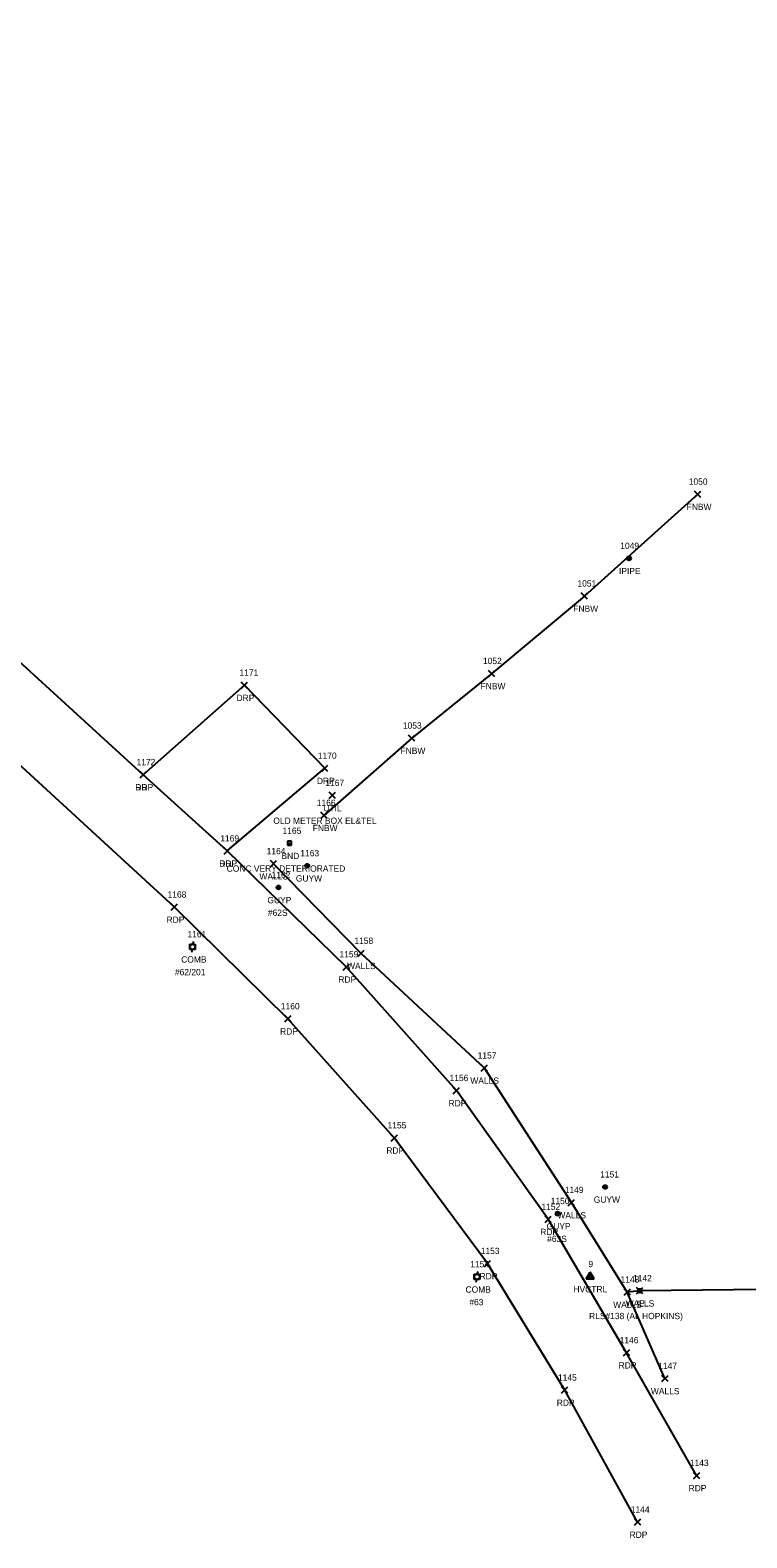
# Model space of a CAD drawing. Extents: x 1519347 to 1522636, y 378779 to 379832.
# Drawn here: x 1521374.1 to 1521601.3, y 378826 to 379303.7 of the extents above; entities that cross this region are included whole.
import ezdxf

# ---------------------------------------------------------------- set-up
doc = ezdxf.new("R2010")
doc.units = 0
for name, color, linetype in [('C_A', 7, 'Continuous'), ('C_I', 7, 'Continuous'), ('CPSM', 7, 'Continuous'), ('L_A', 7, 'Continuous'), ('L_I', 7, 'Continuous'), ('L_TIC', 7, 'Continuous'), ('LFNC', 7, 'Continuous'), ('LWS', 7, 'Continuous'), ('M_A', 7, 'Continuous'), ('M_C', 7, 'Continuous'), ('M_I', 7, 'Continuous'), ('MHBP', 7, 'Continuous'), ('MPIP', 7, 'Continuous'), ('MPIR', 7, 'Continuous'), ('P_A', 7, 'Continuous'), ('P_I', 7, 'Continuous'), ('P_TIC', 7, 'Continuous'), ('PET', 7, 'Continuous'), ('R_A', 7, 'Continuous'), ('R_I', 7, 'Continuous'), ('R_TIC', 7, 'Continuous'), ('RDP', 7, 'Continuous'), ('U_A', 7, 'Continuous'), ('U_C', 7, 'Continuous'), ('U_I', 7, 'Continuous'), ('UDEFAULT', 7, 'Continuous'), ('UP', 7, 'Continuous'), ('UPGW', 7, 'Continuous')]:
    doc.layers.add(name, color=color, linetype=linetype)

msp = doc.modelspace()

# ---------------------------------------------------------------- linework, layer by layer
at = {"layer": 'CPSM'}
for p, q in [((1521550.39, 378908.08), (1521551.64, 378910.25)), ((1521550.39, 378908.08), (1521551.65, 378908.8)), ((1521550.39, 378908.08), (1521552.89, 378908.08)), ((1521552.89, 378908.08), (1521551.64, 378910.25)), ((1521551.65, 378908.8), (1521551.64, 378910.25)), ((1521551.65, 378908.8), (1521551.65, 378908.8)), ((1521551.65, 378908.8), (1521552.89, 378908.08))]:
    msp.add_line(p, q, dxfattribs=at)
at = {"layer": 'L_TIC'}
for points in [[(1521584.74, 379155.69), (1521586.74, 379157.69)], [(1521586.74, 379155.69), (1521584.74, 379157.69)], [(1521548.81, 379123.43), (1521550.81, 379125.43)], [(1521550.81, 379123.43), (1521548.81, 379125.43)], [(1521519.43, 379098.86), (1521521.43, 379100.86)], [(1521521.43, 379098.86), (1521519.43, 379100.86)], [(1521494.06, 379078.4), (1521496.06, 379080.4)], [(1521496.06, 379078.4), (1521494.06, 379080.4)], [(1521466.23, 379053.94), (1521468.23, 379055.94)], [(1521468.23, 379053.94), (1521466.23, 379055.94)], [(1521450.27, 379038.62), (1521452.27, 379040.62)], [(1521452.27, 379038.62), (1521450.27, 379040.62)], [(1521478.03, 379010.22), (1521480.03, 379012.22)], [(1521480.03, 379010.22), (1521478.03, 379012.22)], [(1521517.11, 378973.89), (1521519.11, 378975.89)], [(1521519.11, 378973.89), (1521517.11, 378975.89)], [(1521544.7, 378931.26), (1521546.7, 378933.26)], [(1521546.7, 378931.26), (1521544.7, 378933.26)], [(1521562.39, 378902.89), (1521564.39, 378904.89)], [(1521564.39, 378902.89), (1521562.39, 378904.89)], [(1521562.39, 378902.89), (1521564.39, 378904.89)], [(1521564.39, 378902.89), (1521562.39, 378904.89)], [(1521566.34, 378903.32), (1521568.34, 378905.32)], [(1521568.34, 378903.32), (1521566.34, 378905.32)], [(1521574.33, 378875.52), (1521576.33, 378877.52)], [(1521576.33, 378875.52), (1521574.33, 378877.52)]]:
    msp.add_lwpolyline(points, dxfattribs=at)
at = {"layer": 'LFNC'}
msp.add_lwpolyline([(1521585.74, 379156.69), (1521549.81, 379124.43), (1521520.43, 379099.86), (1521495.06, 379079.4), (1521467.23, 379054.94)], dxfattribs=at)
at = {"layer": 'LWS'}
for points in [[(1521616.94, 378904.79), (1521567.34, 378904.32), (1521563.39, 378903.89), (1521545.7, 378932.26), (1521518.11, 378974.89), (1521479.03, 379011.22), (1521451.27, 379039.62)], [(1521575.33, 378876.52), (1521563.39, 378903.89)]]:
    msp.add_lwpolyline(points, dxfattribs=at)
at = {"layer": 'MHBP'}
for p, q in [((1521456.96, 379046.74), (1521455.71, 379046.74)), ((1521455.71, 379046.74), (1521455.71, 379045.49)), ((1521456.96, 379046.74), (1521455.71, 379046.74)), ((1521455.71, 379046.74), (1521455.71, 379045.49)), ((1521456.96, 379045.49), (1521456.96, 379046.74)), ((1521456.96, 379045.49), (1521456.96, 379046.74)), ((1521455.71, 379045.49), (1521456.96, 379045.49)), ((1521455.71, 379045.49), (1521456.96, 379045.49))]:
    msp.add_line(p, q, dxfattribs=at)
msp.add_circle((1521456.31, 379046.08), 0.0833, dxfattribs=at)
at = {"layer": 'MPIP'}
for radius in [0.625, 0.0833]:
    msp.add_circle((1521563.95, 379136.36), radius, dxfattribs=at)
at = {"layer": 'MPIR'}
for radius in [0.625, 0.0833]:
    msp.add_circle((1521567.34, 378904.32), radius, dxfattribs=at)
at = {"layer": 'P_TIC'}
for points in [[(1521408.99, 379066.83), (1521410.99, 379068.83)], [(1521410.99, 379066.83), (1521408.99, 379068.83)], [(1521435.59, 379042.66), (1521437.59, 379044.66)], [(1521437.59, 379042.66), (1521435.59, 379044.66)], [(1521418.87, 379024.89), (1521420.87, 379026.89)], [(1521420.87, 379024.89), (1521418.87, 379026.89)], [(1521473.33, 379005.93), (1521475.33, 379007.93)], [(1521475.33, 379005.93), (1521473.33, 379007.93)], [(1521454.86, 378989.48), (1521456.86, 378991.48)], [(1521456.86, 378989.48), (1521454.86, 378991.48)], [(1521508.26, 378966.74), (1521510.26, 378968.74)], [(1521510.26, 378966.74), (1521508.26, 378968.74)], [(1521488.55, 378951.75), (1521490.55, 378953.75)], [(1521490.55, 378951.75), (1521488.55, 378953.75)], [(1521537.32, 378925.95), (1521539.32, 378927.95)], [(1521539.32, 378925.95), (1521537.32, 378927.95)], [(1521518.09, 378911.94), (1521520.09, 378913.94)], [(1521520.09, 378911.94), (1521518.09, 378913.94)], [(1521562.15, 378883.68), (1521564.15, 378885.68)], [(1521564.15, 378883.68), (1521562.15, 378885.68)], [(1521542.56, 378871.83), (1521544.56, 378873.83)], [(1521544.56, 378871.83), (1521542.56, 378873.83)], [(1521584.34, 378844.78), (1521586.34, 378846.78)], [(1521586.34, 378844.78), (1521584.34, 378846.78)], [(1521565.64, 378830.03), (1521567.64, 378832.03)], [(1521567.64, 378830.03), (1521565.64, 378832.03)]]:
    msp.add_lwpolyline(points, dxfattribs=at)
at = {"layer": 'PET'}
for points in [[(1521585.34, 378845.78), (1521563.15, 378884.68), (1521538.32, 378926.95), (1521509.26, 378967.74), (1521474.33, 379006.93), (1521436.59, 379043.66), (1521409.99, 379067.83), (1521358.14, 379115.1), (1521306.99, 379161.95), (1521255.2, 379209.61), (1521217.12, 379244.56), (1521164.23, 379293.24), (1521067.69, 379382.51), (1520997.97, 379446.49), (1520922.59, 379515.2), (1520874.63, 379556.58), (1520808.13, 379606.22), (1520782.76, 379623.68), (1520756.28, 379641.62), (1520757.14, 379649.49)], [(1521566.64, 378831.03), (1521543.56, 378872.83), (1521519.09, 378912.94), (1521489.55, 378952.75), (1521455.86, 378990.48), (1521419.87, 379025.89), (1521341.37, 379097.91), (1521290.76, 379143.7), (1521238.48, 379191.54), (1521199.1, 379228.33), (1521145.7, 379275.98), (1521050.75, 379364.16), (1520980.24, 379428.62), (1520906.12, 379495.86), (1520857.57, 379538.26), (1520794, 379586.56), (1520766.68, 379604.35), (1520729.49, 379628.42), (1520699.13, 379644.75)]]:
    msp.add_lwpolyline(points, dxfattribs=at)
at = {"layer": 'R_TIC'}
for points in [[(1521441.06, 379095.16), (1521443.06, 379097.16)], [(1521443.06, 379095.16), (1521441.06, 379097.16)], [(1521466.54, 379068.85), (1521468.54, 379070.85)], [(1521468.54, 379068.85), (1521466.54, 379070.85)], [(1521408.99, 379066.83), (1521410.99, 379068.83)], [(1521410.99, 379066.83), (1521408.99, 379068.83)], [(1521435.59, 379042.66), (1521437.59, 379044.66)], [(1521437.59, 379042.66), (1521435.59, 379044.66)]]:
    msp.add_lwpolyline(points, dxfattribs=at)
at = {"layer": 'RDP'}
msp.add_lwpolyline([(1521436.59, 379043.66), (1521467.54, 379069.85), (1521442.06, 379096.16), (1521409.99, 379067.83)], dxfattribs=at)
at = {"layer": 'UDEFAULT'}
for points in [[(1521468.88, 379060.24), (1521470.88, 379062.24)], [(1521470.88, 379060.24), (1521468.88, 379062.24)]]:
    msp.add_lwpolyline(points, dxfattribs=at)
at = {"layer": 'UP'}
for p, q in [((1521424.79, 379012.45), (1521424.79, 379014.12)), ((1521424.79, 379014.12), (1521426.46, 379014.12)), ((1521425.87, 379014.95), (1521425.62, 379014.12)), ((1521425.62, 379013.29), (1521425.62, 379013.29)), ((1521426.46, 379014.12), (1521426.46, 379012.45)), ((1521426.46, 379012.45), (1521424.79, 379012.45)), ((1521425.37, 379011.62), (1521425.62, 379012.45)), ((1521514.91, 378907.89), (1521514.91, 378909.56)), ((1521514.91, 378909.56), (1521516.57, 378909.56)), ((1521516.57, 378907.89), (1521514.91, 378907.89)), ((1521515.49, 378907.06), (1521515.74, 378907.89)), ((1521515.99, 378910.39), (1521515.74, 378909.56)), ((1521515.74, 378908.72), (1521515.74, 378908.72)), ((1521516.57, 378909.56), (1521516.57, 378907.89))]:
    msp.add_line(p, q, dxfattribs=at)
for centre in [(1521425.62, 379013.29), (1521515.74, 378908.72)]:
    msp.add_circle(centre, 0.833, dxfattribs=at)
at = {"layer": 'UPGW'}
for centre, radius in [((1521461.95, 379038.97), 0.625), ((1521461.95, 379038.97), 0.0833), ((1521452.84, 379032.09), 0.625), ((1521452.84, 379032.09), 0.0833), ((1521556.37, 378937.2), 0.625), ((1521556.37, 378937.2), 0.0833), ((1521541.33, 378928.76), 0.625), ((1521541.33, 378928.76), 0.0833)]:
    msp.add_circle(centre, radius, dxfattribs=at)

# ---------------------------------------------------------------- texts
at = {"layer": 'C_A'}
msp.add_text('HVCTRL', height=2, dxfattribs=at).set_placement((1521546.34, 378903.8))
at = {"layer": 'C_I'}
msp.add_text('9', height=2, dxfattribs=at).set_placement((1521551.07, 378911.8))
at = {"layer": 'L_A'}
for s, p in [('FNBW', (1521582.21, 379151.69)), ('FNBW', (1521546.28, 379119.43)), ('FNBW', (1521516.9, 379094.86)), ('FNBW', (1521491.53, 379074.4)), ('FNBW', (1521463.7, 379049.94)), ('WALLS', (1521446.81, 379034.62)), ('WALLS', (1521474.58, 379006.22)), ('WALLS', (1521513.65, 378969.89)), ('WALLS', (1521541.25, 378927.26)), ('WALLS', (1521558.93, 378898.89)), ('WALLS', (1521558.93, 378898.89)), ('WALLS', (1521562.88, 378899.32)), ('WALLS', (1521570.87, 378871.52))]:
    msp.add_text(s, height=2, dxfattribs=at).set_placement(p)
at = {"layer": 'L_I'}
for s, p in [('1050', (1521582.88, 379159.69)), ('1051', (1521547.6, 379127.43)), ('1052', (1521517.66, 379102.86)), ('1053', (1521492.28, 379082.4)), ('1166', (1521465, 379057.94)), ('1164', (1521449.1, 379042.62)), ('1158', (1521476.91, 379014.22)), ('1157', (1521515.98, 378977.89)), ('1149', (1521543.57, 378935.26)), ('1148', (1521561.26, 378906.89)), ('1148', (1521561.26, 378906.89)), ('1142', (1521565.21, 378907.32)), ('1147', (1521573.2, 378879.52))]:
    msp.add_text(s, height=2, dxfattribs=at).set_placement(p)
at = {"layer": 'M_A'}
for s, p in [('IPIPE', (1521560.78, 379131.36)), ('BND', (1521453.8, 379041.08)), ('IP', (1521566.39, 378899.32))]:
    msp.add_text(s, height=2, dxfattribs=at).set_placement(p)
at = {"layer": 'M_C'}
for s, p in [('CONC VERY DETERIORATED', (1521436.43, 379037.08)), ('RLS#138 (AL HOPKINS)', (1521551.28, 378895.32))]:
    msp.add_text(s, height=2, dxfattribs=at).set_placement(p)
at = {"layer": 'M_I'}
for s, p in [('1049', (1521561.17, 379139.36)), ('1165', (1521454.13, 379049.08)), ('1142', (1521565.21, 378907.32))]:
    msp.add_text(s, height=2, dxfattribs=at).set_placement(p)
at = {"layer": 'P_A'}
for p in [(1521407.48, 379062.83), (1521434.08, 379038.66), (1521417.36, 379020.89), (1521471.82, 379001.93), (1521453.35, 378985.48), (1521506.75, 378962.74), (1521487.04, 378947.75), (1521535.81, 378921.95), (1521516.58, 378907.94), (1521560.64, 378879.68), (1521541.05, 378867.83), (1521582.83, 378840.78), (1521564.12, 378826.03)]:
    msp.add_text('RDP', height=2, dxfattribs=at).set_placement(p)
at = {"layer": 'P_I'}
for s, p in [('1172', (1521407.87, 379070.83)), ('1169', (1521434.41, 379046.66)), ('1168', (1521417.7, 379028.89)), ('1159', (1521472.19, 379009.93)), ('1160', (1521453.6, 378993.48)), ('1156', (1521507.08, 378970.74)), ('1155', (1521487.42, 378955.75)), ('1152', (1521536.2, 378929.95)), ('1153', (1521516.96, 378915.94)), ('1146', (1521560.97, 378887.68)), ('1145', (1521541.43, 378875.83)), ('1143', (1521583.22, 378848.78)), ('1144', (1521564.51, 378834.03))]:
    msp.add_text(s, height=2, dxfattribs=at).set_placement(p)
at = {"layer": 'R_A'}
for p in [(1521439.55, 379091.16), (1521465.03, 379064.85), (1521407.48, 379062.83), (1521434.08, 379038.66)]:
    msp.add_text('DRP', height=2, dxfattribs=at).set_placement(p)
at = {"layer": 'R_I'}
for s, p in [('1171', (1521440.5, 379099.16)), ('1170', (1521465.33, 379072.85)), ('1172', (1521407.87, 379070.83)), ('1169', (1521434.41, 379046.66))]:
    msp.add_text(s, height=2, dxfattribs=at).set_placement(p)
at = {"layer": 'U_A'}
for s, p in [('UTIL', (1521467.05, 379056.24)), ('GUYW', (1521458.35, 379033.97)), ('GUYP', (1521449.36, 379027.09)), ('COMB', (1521422.01, 379008.29)), ('GUYW', (1521552.76, 378932.2)), ('GUYP', (1521537.85, 378923.76)), ('COMB', (1521512.13, 378903.72))]:
    msp.add_text(s, height=2, dxfattribs=at).set_placement(p)
at = {"layer": 'U_C'}
for s, p in [('OLD METER BOX EL&TEL', (1521451.22, 379052.24)), ('#62S', (1521449.49, 379023.09)), ('#62/201', (1521420.03, 379004.29)), ('#63S', (1521537.98, 378919.76)), ('#63', (1521513.33, 378899.72))]:
    msp.add_text(s, height=2, dxfattribs=at).set_placement(p)
at = {"layer": 'U_I'}
for s, p in [('1167', (1521467.71, 379064.24)), ('1163', (1521459.78, 379041.97)), ('1162', (1521450.67, 379035.09)), ('1161', (1521424.02, 379016.29)), ('1151', (1521554.81, 378940.2)), ('1150', (1521539.12, 378931.76)), ('1154', (1521513.62, 378911.72))]:
    msp.add_text(s, height=2, dxfattribs=at).set_placement(p)

doc.saveas('drawing.dxf')
